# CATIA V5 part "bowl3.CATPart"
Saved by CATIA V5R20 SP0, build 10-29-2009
Part number: bowl3
Material "Grey Blue": density 7860 kg/m3, Young's modulus 2e+11 Pa, Poisson ratio 0.266
Bounding box of the stored display mesh (mm): x -60 to 60, y -60 to 59.999, z 0 to 40
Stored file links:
  E:\设计\180212313林恺昇\bowl3.CATPart
  E:\设计\180212313林恺昇\Product1.CATProduct
  E:\设计\180212313林恺昇\cart3.CATPart
  C:\Program Files\Dassault Systemes\B20\intel_a\startup\materials\Catalog.CATMaterial
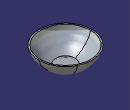
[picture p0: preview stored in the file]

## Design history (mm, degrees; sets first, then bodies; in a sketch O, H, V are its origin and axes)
Body1 (main body)
  Sketch1 on xy-plane, origin (0, 0, 0), H (1, 0, 0), V (0, 1, 0)
    circle A1 centre (0, 0) radius 22.5
    radius A1 = 22.5
  Plane1: type Offset, RefPlane xy-plane, Offset 10
  Plane2: type Offset, RefPlane Plane1, Offset 10
  Plane3: type Offset, RefPlane Plane2, Offset 10
  Plane4: type Offset, RefPlane Plane3, Offset 10
  Sketch2 on Plane4, origin (0, 0, 40), H (1, 0, 0), V (0, 1, 0)
    circle A1 centre (0, 0) radius 60
    radius A1 = 60
  Sketch3 on Plane3, origin (0, 0, 30), H (1, 0, 0), V (0, 1, 0)
    circle A1 centre (0, 0) radius 56.5
    radius A1 = 56.5
  Sketch4 on Plane2, origin (0, 0, 20), H (1, 0, 0), V (0, 1, 0)
    circle A1 centre (0, 0) radius 49
    radius A1 = 49
  Sketch5 on Plane1, origin (0, 0, 10), H (1, 0, 0), V (0, 1, 0)
    circle A1 centre (0, 0) radius 40
    radius A1 = 40
  Loft1: solid, Sections (Sketch2; Sketch3; Sketch4; Sketch5; Sketch1)
  Shell1: ExtOffset 0, Face face of Loft1, IntOffset 3
  Sketch6 on face of Loft1, origin (0, 0, 0), H (1, 0, 0), V (0, -1, 0)
    circle A1 centre (0, 0) radius 20
    radius A1 = 20
  Pocket1: profile Sketch6, direction (0, 0, 1), length 2
  Fillet1: radius 1, on edge [face of Pocket1 from Sketch6.A1 | end face of Pocket1]
  Fillet2: radius 1, on edge [face of Loft1 | face of Pocket1 from Sketch6.A1]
